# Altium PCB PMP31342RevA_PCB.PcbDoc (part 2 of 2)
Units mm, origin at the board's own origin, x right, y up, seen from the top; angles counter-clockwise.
Board outline 170.18 x 93.98 mm, 4 copper layers (Top Layer, Layer 1, Layer 2, Bottom Layer), stack 1.787 mm thick; 134 components, 50 nets, 251 pads, 234 vias.
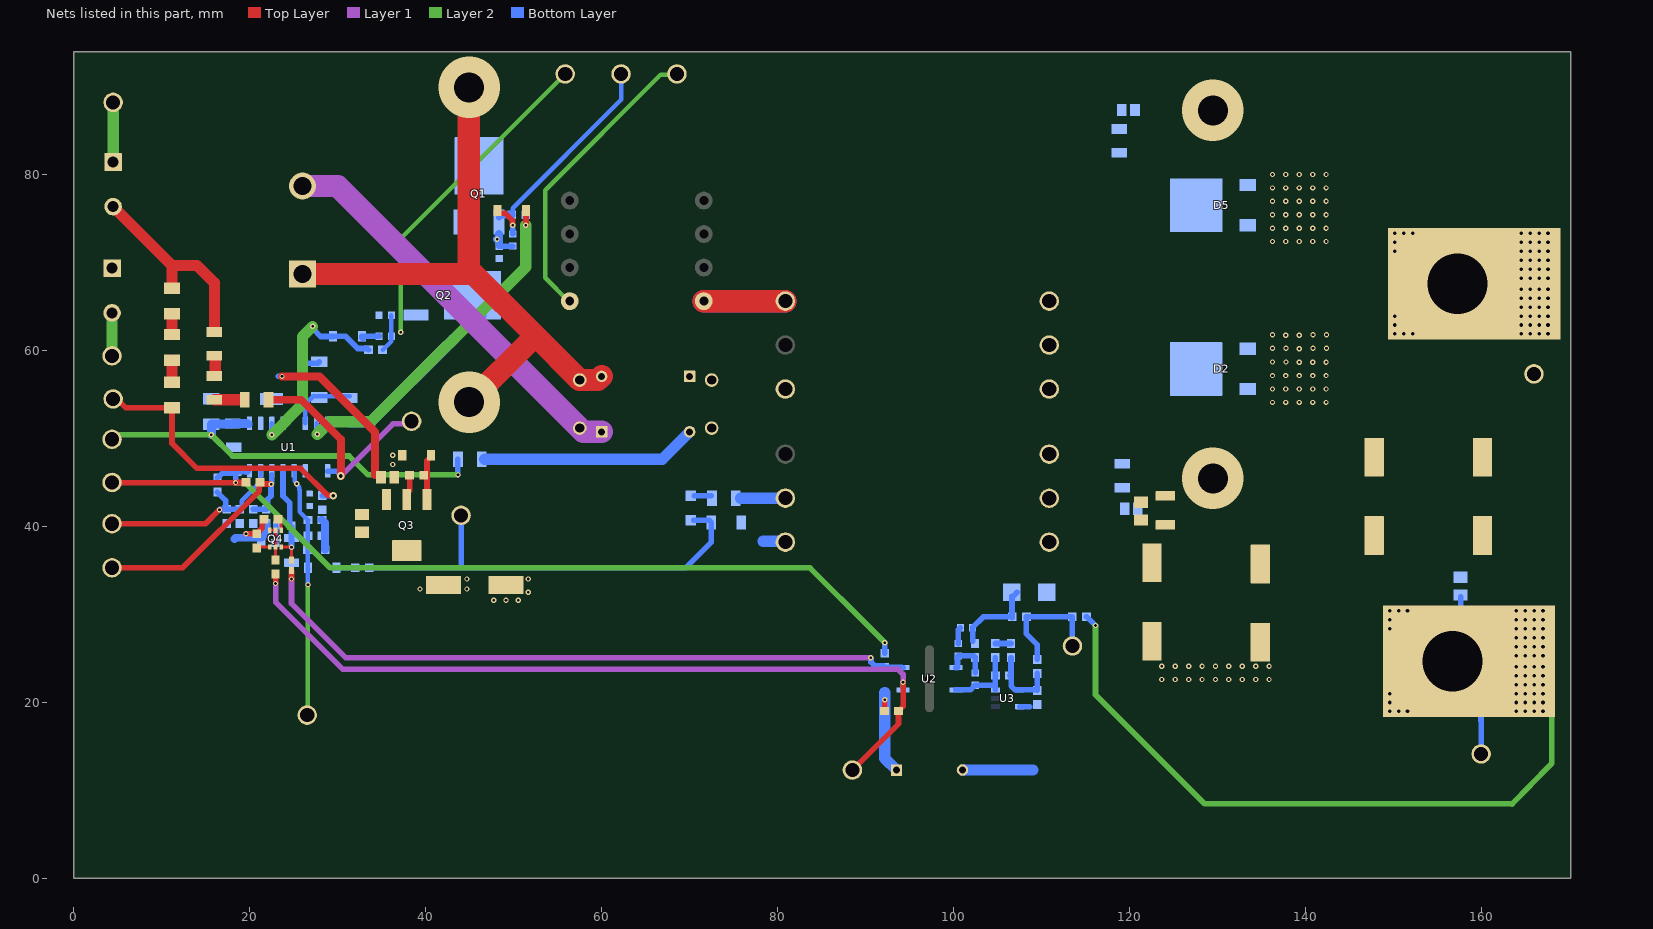
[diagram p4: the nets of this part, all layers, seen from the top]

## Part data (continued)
R31: library part CMP-0022981-5, "RES, 2.05 k, 1%, 0.1 W, 0603", Manufacturer=Yageo, Power_W=100mW, Supplier Part Number 1=311-2.05KHRCT-ND, TempCo="100 ppm/C", Tolerance_%=1%, Value2=0.1W, Value_Code=2k05, ValueDisplayed=2.05k
R32: library part CMP-0022458-4, "RES, 4.99 k, 1%, 0.1 W, AEC-Q200 Grade 0, 0603", Manufacturer=Vishay-Dale, Power_W=100mW, Supplier Part Number 1=541-4.99KHCT-ND, TempCo="100 ppm/C", Tolerance_%=1%, Value2=0.1W, Value_Code=4k99, ValueDisplayed=DNP
R33 R39: library part CMP-0023441-3, "RES, 15.0 k, 0.1%, 0.1 W, 0603", Manufacturer="Susumu Co Ltd", Power_W=100mW, Supplier Part Number 1=RG16P15.0KBCT-ND, TempCo="25 ppm/C", Tolerance_%=0.1%, Value2=0.1W, Value_Code=15k0, ValueDisplayed=15.0k
R34: library part CMP-0022589-4, "RES, 75.0 k, 1%, 0.1 W, AEC-Q200 Grade 0, 0603", Manufacturer=Vishay-Dale, Power_W=100mW, Supplier Part Number 1=541-75.0KHCT-ND, TempCo="100 ppm/C", Tolerance_%=1%, Value2=0.1W, Value_Code=75k0, ValueDisplayed=75.0k
R35: library part CMP-0025697-4, "RES, 0, 5%, 0.1 W, AEC-Q200 Grade 0, 0603", Manufacturer=Vishay-Dale, Power_W=100mW, Supplier Part Number 1=541-0.0GCT-ND, TempCo="200 ppm/C", Tolerance_%=5%, Value2=0.1W, Value_Code=0000, ValueDisplayed=0
R36 R41 R42: library part CMP-0025697-4, "RES, 0, 5%, 0.1 W, AEC-Q200 Grade 0, 0603", Manufacturer=Vishay-Dale, Power_W=100mW, Supplier Part Number 1=541-0.0GCT-ND, TempCo="200 ppm/C", Tolerance_%=5%, Value2=0.1W, Value_Code=0000, ValueDisplayed=DNP
R37: library part CMP-0022634-4, "RES, 8.06 k, 1%, 0.1 W, AEC-Q200 Grade 0, 0603", Manufacturer=Vishay-Dale, Power_W=100mW, Supplier Part Number 1=541-8.06KHCT-ND, TempCo="100 ppm/C", Tolerance_%=1%, Value2=0.1W, Value_Code=8k06, ValueDisplayed=8.06k
R38: library part CMP-0096703-1, "NTC Thermistor 470k 0603 (1608 Metric)", B Tolerance=3%, Digikey Part Number=495-B57371V2474J060CT-ND, Manufacturer=TDK, Mouser Part Number=871-B57371V2474J060, Operating Temperature Range="-55°C to +125°C", Power_W=180mW, Tolerance_%=5%
R40: library part CMP-0022268-4, "RES, 2.00 k, 1%, 0.1 W, AEC-Q200 Grade 0, 0603", Manufacturer=Vishay-Dale, Power_W=100mW, Supplier Part Number 1=541-2.00KHCT-ND, TempCo="100 ppm/C", Tolerance_%=1%, Value2=0.1W, Value_Code=2k00, ValueDisplayed=2.00k
T2 T3: library part CMP-0075010-2, "Terminal 70A Lug", Manufacturer=Panduit, Supplier Part Number 1=CXS70-14-C-ND
TP1 TP2 TP3 TP6 TP7 TP8 TP9 TP10 TP11 TP12 TP13 TP14: library part CMP-0055157-2, "Test Point, Multipurpose, Brown, TH", Color=Brown, Manufacturer="Keystone Electronics", Supplier Part Number 1=36-5125-ND
TP4 TP5 TP15 TP16 TP17 TP18 TP19 TP20: library part CMP-0055140-2, "Test Point, Miniature, Orange, TH", Color=Orange, Manufacturer="Keystone Electronics", Supplier Part Number 1=36-5003-ND
U1: library part CMP-0095298-2, "750kHz Wide VIN/VOUT Range LLC Controller Optimized for Light Load Efficiency", Manufacturer="Texas Instruments", Max Supply Voltage=18.5V, Operating Temperature Range="-40°C to +150°C", PartNumber=UCC256612DDBR, Switching Frequency=30-750kHz
U2: library part CMP-0098363-1, "3.75-kVRMS, Single-Channel Opto-Emulator with Transistor Output", Emiiter Collector Voltage=7V, Forward Current=10mA, Manufacturer="Texas Instruments", Operating Temperature Range="to +150°C", Power_TotalModule=200mW, Voltage_Isolation_Vrms=3750Vrms
U3: library part CMP-0032955-1, "Automotive Catalog Low-Voltage Adjustable Precision Shunt Regulator, 80 mA, -40 to 125 degC, 5-pin SOT-23 (DBV), Green (RoHS & no Sb/Br)", Manufacturer="Texas Instruments", Rating=Automotive, Temp Coeff(Max)(ppm/ degree C)=129

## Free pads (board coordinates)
  oval 1.016x7.62 hole 1.016 slot 7.62 at 90 deg unplated mask+0.127: 3(97.282,22.689)

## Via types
v1: diameter 0.813, hole 0.406, Top Layer to Bottom Layer, 116 vias
v2: diameter 0.6, hole 0.3, Top Layer to Bottom Layer, 112 vias
v3: diameter 7, hole 3.4, Top Layer to Bottom Layer, 4 vias
v4: diameter 0.864, hole 0.406, Top Layer to Bottom Layer, 2 vias

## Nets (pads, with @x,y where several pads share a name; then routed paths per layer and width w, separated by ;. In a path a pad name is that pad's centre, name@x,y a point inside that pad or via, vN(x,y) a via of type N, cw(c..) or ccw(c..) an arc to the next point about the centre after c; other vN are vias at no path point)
5VP: 5V.1 C20.1 R21.2 R22.2 R24.2 U1.8 | length 102.7
  Top Layer w0.635: 5V.1@4.276,44.986 v2(18.41,44.986) 18.421,44.997 19.586,44.997 R22.2@19.596,45.008
  Layer 2 w0.635: v2(18.41,44.986) 19.476,44.986 29.168,35.295 83.704,35.295 90.437,28.562 v2(92.202,26.797)
  Bottom Layer w0.635: R21.2@16.347,45.503 16.347,45.528 16.505,45.685 16.53,45.685 16.91,46.065 18.284,46.065 18.324,46.105 18.42,46.009 18.42,44.996 v2(18.41,44.986) ; R24.2@92.202,25.589 v2(92.202,26.797)
  Bottom Layer w0.889: C20.1@18.324,46.105 C20.1@18.429,46.21 ; C20.1@18.434,46.356 U1.8@19.69,46.316
FB: C27.1 Q4.6 R27.1 R32.2 U1.5 | length 11.7
  Top Layer w0.305: Q4.6@23.601,37.672 23.611,37.662 24.758,37.662 v2(24.768,37.652) R27.1@24.768,36.188
  Bottom Layer w0.635: U1.5@23.798,46.316 23.798,43.466 24.586,42.678 24.586,40.11 24.61,40.11 24.768,39.953 C27.1@24.768,38.688 v2(24.768,37.652)
HO: D1.1 R1.1 U1.15 | length 40.5
  Top Layer w0.635: v2(51.397,74.231) 51.416,74.25 51.416,75.888 D1.1@51.434,75.907
  Layer 2 w1.27: v2(27.691,50.482) 29.117,51.908 33.811,51.908 51.397,69.493 v2(51.397,74.231)
  Bottom Layer w0.508: U1.15@27.608,51.716 27.65,51.675 27.65,50.524 v2(27.691,50.482)
  Bottom Layer w0.635: v2(51.397,74.231) R1.1@51.397,75.432
HS: C21.2 Q1.3 Q2.4 R4.1 SW.1 TP4.1 U1.16 | length 52.3
  Layer 2 w0.508: TP4.1@56.391,65.616 56.25,65.616 53.597,68.269 53.597,78.235 66.713,91.351 68.491,91.351 SW.1@68.58,91.44
  Bottom Layer w0.508: Q2.4@46.698,63.837 Q2.4@46.698,64.066
  Bottom Layer w0.635: 29.178,51.716 C21.2@31.267,51.716
  Bottom Layer w1.27: C21.2@31.369,51.908 33.811,51.908 43.125,61.222 43.157,61.222
ISNS: C7.2 C14.1 ISNS.1 R10.2 U1.9 | length 48.7
  Layer 2 w0.635: ISNS.1@4.334,49.855 4.739,49.855 5.306,50.422 v2(15.646,50.422) 18.063,48.006 31.32,48.006 33.467,45.859 v2(43.684,45.859)
  Bottom Layer w0.635: U1.9@19.972,51.533 19.99,51.55 U1.9@19.99,51.716 ; v2(43.684,45.859) C7.2@43.684,47.648
  Bottom Layer w1.016: v2(15.646,50.422) R10.2@15.646,51.533 ; R10.2@15.646,51.595 15.713,51.662 18.052,51.662 C14.1@18.085,51.695 U1.9@19.69,51.716
LO: D4.1 R6.1 U1.11 | length 23.1
  Layer 2 w1.27: v2(22.53,50.422) 26.016,53.908 26.016,61.594 v2(27.166,62.744)
  Bottom Layer w0.508: v2(22.53,50.422) v2(22.53,50.422) 22.529,51.715 U1.11@22.53,51.716
  Bottom Layer w0.635: v2(27.166,62.744) 27.19,62.72 27.19,62.484 28.08,61.594 D4.1@29.458,61.594 ; D4.1@29.49,61.626 30.9,61.626 32.301,60.226 33.363,60.226 R6.1@33.521,60.068
NetBLK_1: BLK.1 C23.2 R20.1 R28.2 U1.3 | length 33.2
  Top Layer w0.635: BLK.1@4.496,54.499 4.922,54.499 5.913,53.508 R20.1@11.176,53.508 11.176,49.457 14.03,46.603 25.796,46.603 28.853,43.546 29.448,43.546 v4(29.491,43.502)
  Layer 2 w0.635: v4(29.491,43.502) v4@29.534,43.459
  Bottom Layer w0.635: R28.2@28.245,43.508 28.248,43.505 29.489,43.505 v4(29.491,43.502)
NetC1_2: C1.2 C7.1 C12.1 TP3.1 | length 24.6
  Bottom Layer w1.27: C7.1@46.734,47.648 66.912,47.648 C1.2@70.024,50.76
NetC2_1: C2.1 R2.1
NetC16_1: C16.1 R7.1
NetC21_1: C21.1 D7.1 U1.14 | length 7.6
  Bottom Layer w0.508: U1.14@26.34,51.716 26.34,53.918 27.229,54.808 C21.1@31.369,54.808
NetC22_1: C22.1 D8.1 R25.2 R26.1 | length 9.8
  Bottom Layer w0.635: R25.2@102.192,26.965 C22.1@102.192,28.501 102.192,28.526 103.406,29.74 R26.1@106.667,29.74 ; R26.1@106.667,29.611 R26.1@106.667,29.74 ; D8.1@106.667,32.068 D8.1@106.667,31.941 ; R26.1@106.7,29.74 R26.1@106.667,29.74 ; D8.1@107.232,32.506 D8.1@106.667,31.941 ; R26.1@106.667,29.74 D8.1@106.667,31.941
NetC22_2: C22.2 R19.2 | length 1.9
  Bottom Layer w0.635: R19.2@100.572,26.691 100.572,28.256 100.792,28.476 C22.2@100.792,28.501
NetC24_1: C24.1 LL.1 R22.1 R30.2 U1.6 | length 29.5
  Top Layer w0.635: LL.1@4.369,35.306 12.387,35.306 21.116,44.035 21.116,44.744 21.166,44.794 v2(22.457,44.794) 22.423,44.794 22.366,44.85 21.354,44.85 R22.1@21.196,45.008
  Bottom Layer w0.635: R30.2@20.396,41.953 21.92,41.953 22.033,42.066 22.033,43.066 22.433,43.465 22.433,44.769 v2(22.457,44.794) 22.457,44.828 22.53,44.901 U1.6@22.53,45.859
NetC25_1: C25.1 R21.1 R29.2 TSET.1 U1.7 | length 22.5
  Top Layer w0.635: TSET.1@4.369,40.311 14.999,40.311 v2@16.597,41.908
  Bottom Layer w0.508: C25.1@18.877,41.953 19.098,42.174 19.098,42.924 21.258,45.084 U1.7@21.258,46.316
  Bottom Layer w0.635: R21.1@16.347,43.903 16.347,43.878 17.271,42.954 R29.2@17.271,42.346 ; v2(16.579,41.908) 16.614,41.908 16.676,41.97 C25.1@18.877,41.97
NetC26_1: C26.1 D9.2 OVP_OTP.1 R38.2 R39.2 U1.4 | length 28.2
  Top Layer w0.508: OVP_OTP.1@26.551,18.553 OVP_OTP.1@26.598,18.6 ; v2@26.598,33.312 v2(26.645,33.359)
  Layer 2 w0.508: OVP_OTP.1@26.598,18.6 v2@26.598,33.312
  Bottom Layer w0.508: U1.4@25.07,46.316 25.116,46.27 25.116,45.156 25.355,44.917 v2(25.355,44.848) 25.355,44.78 25.665,44.47 25.665,44.167 ; 25.685,41.671 25.685,44.147 ; 25.882,41.473 26.62,40.735 C26.1@26.645,40.735 26.618,40.708 26.618,38.962 26.618,37.389 26.608,37.38 26.608,35.208 26.645,35.171 26.635,35.161 26.635,33.369 v2(26.645,33.359)
NetC28_1: C28.1 R34.1 R37.2 R40.2 U3.4 | length 8.2
  Bottom Layer w0.635: C28.1@106.388,23.057 106.413,23.057 106.57,22.9 106.57,21.874 107.026,21.419 U3.4@107.526,21.419 109.48,21.419 R40.2@109.529,21.371 R34.1@109.529,23.285 ; C28.1@106.55,23.215 R37.2@106.55,25.093
NetC28_2: C28.2 C30.2 R31.1 U2.2 U3.3 | length 9.5
  Bottom Layer w0.635: U2.2@100.282,21.419 101.932,21.419 102.356,21.843 102.356,21.868 102.439,21.951 R31.1@102.464,21.951 104.776,21.951 C30.2@104.776,25.093 ; U3.3@104.776,21.419 104.782,21.425 104.782,23.051 C28.2@104.788,23.057
NetC29_1: C29.1 R32.1 | length 2
  Bottom Layer w0.635: C29.1@22.916,38.127 22.951,38.162 22.951,40.076 R32.1@22.986,40.11
NetC30_1: C30.1 R37.1 | length 1.8
  Bottom Layer w0.635: C30.1@104.776,26.693 R37.1@106.55,26.693
NetD1_2: D1.2 R3.1 | length 3.8
  Top Layer w0.635: D1.2@48.159,75.907 48.159,75.755 48.299,75.615 49.047,75.615 49.887,74.775 49.887,74.256 v2(49.911,74.231)
  Bottom Layer w0.635: v2(49.911,74.231) 49.914,74.229 49.914,73.262 R3.1@49.917,73.259 R3.1@49.942,73.259
NetD3_2: D3.2 R5.1 | length 1.9
  Bottom Layer w0.635: D3.2@70.561,43.507 R5.1@72.464,43.507
NetD4_2: D4.2 R8.1 | length 2.3
  Bottom Layer w0.635: D4.2@32.905,61.334 32.765,61.474 D4.2@32.765,61.626 32.775,61.636 34.71,61.636 R8.1@34.721,61.647
NetD6_1: D6.1 Q3.1 R12.1 | length 5.2
  Top Layer w0.635: Q3.1@40.166,43.054 40.166,47.47 40.626,47.931 D6.1@40.626,48.084
NetD7_2: D7.2 R13.2 | length 2.2
  Bottom Layer w0.635: R13.2@25.886,58.452 25.969,58.535 27.748,58.535 D7.2@27.94,58.727
NetD9_1: D9.1 R33.1 | length 2.1
  Bottom Layer w0.635: D9.1@29.901,35.295 R33.1@32.011,35.295 R33.1@31.999,35.307
NetHG_1: HG.1 Q1.1 R1.2 R3.2 R4.2 | length 25.3
  Bottom Layer w0.305: R1.2@49.797,75.432 R1.2@49.897,75.532
  Bottom Layer w0.508: R1.2@49.897,75.532 49.897,76.186 62.23,88.519 HG.1@62.23,91.44
  Bottom Layer w0.635: R4.2@48.356,71.848 48.361,71.854 49.911,71.854 R3.2@49.917,71.859 ; Q1.1@48.356,75.125 Q1.1@48.663,75.432
  Bottom Layer w0.889: v2(48.133,72.644) v2@48.14,72.644 ; R4.2@48.356,72.229 Q1.1@48.356,73.24 ; Q1.1@48.663,75.432 R1.2@49.797,75.432
NetHV_1: HV.1 R17.2 U1.1 | length 26.9
  Top Layer w0.889: R17.2@22.155,54.408 25.882,54.408 30.378,49.911 v4(30.378,45.733)
  Layer 1 w0.635: v4(30.378,45.733) 36.3,51.655 38.118,51.655 HV.1@38.419,51.956
  Layer 2 w0.508: v4(30.378,45.733) v4@30.475,45.733
  Bottom Layer w0.635: U1.1@28.895,46.288 29.932,46.288 30.13,46.09 30.13,46.043 30.378,45.795 v4(30.378,45.733) ; HV.1@38.419,51.85 HV.1@38.546,51.723
NetI_opt_1: I_opt.1 R35.2 R36.2 U2.3 | length 91.7
  Top Layer w0.635: v2(22.951,33.522) R36.2@22.951,34.588 ; I_opt.1@88.519,12.313 93.764,17.558 R35.2@93.764,19.028 93.789,19.028 93.946,19.185 93.946,19.21 94.282,19.546 v2(94.282,22.277)
  Layer 1 w0.635: v2(22.951,33.522) 22.951,31.405 30.607,23.749 93.717,23.749 94.282,23.184 v2(94.282,22.277)
  Bottom Layer w0.635: 94.282,21.719 v2(94.282,22.277)
NetINJ_1: Inj.1 R23.1 R26.2 R34.2 | length 13.9
  Bottom Layer w0.635: R26.2@108.3,29.74 108.3,27.791 109.529,26.562 R34.2@109.529,24.885 ; R26.2@108.3,29.749 R23.1@113.519,29.749 113.529,29.74 113.529,26.42 Inj.1@113.538,26.41
NetLG_1: LG.1 Q2.1 R6.2 R8.2 R9.2 | length 41.5
  Layer 2 w0.508: v2(37.181,62.077) 37.181,72.741 LG.1@55.88,91.44
  Bottom Layer w0.508: R6.2@35.121,60.068 35.146,60.068 36.121,61.043 R8.2@36.121,61.647 R9.2@36.121,64.009
NetQ4_1: Q4.1 R41.2 | length 1.4
  Top Layer w0.305: R41.2@23.223,40.801 23.248,40.801 23.57,40.479 23.57,39.603 Q4.1@23.601,39.572
NetQ4_2: Q4.2 Q4.3 Q4.5 R36.1 | length 3.9
  Top Layer w0.305: Q4.3@22.301,39.572 22.797,39.572 22.951,39.418 Q4.5@22.951,37.672 R36.1@22.951,36.188
NetQ4_4: Q4.4 R42.2 | length 1.5
  Top Layer w0.305: R42.2@20.816,37.566 20.922,37.672 Q4.4@22.301,37.672
NetR5_2: R5.2 TP12.1 | length 5.1
  Bottom Layer w1.27: R5.2@75.812,43.216 TP12.1@80.899,43.216
NetR14_1: R14.1 R18.2 | length 2.4
  Top Layer w1.27: R18.2@11.176,61.818 R14.1@11.176,64.178
NetR15_2: R15.2 R16.1 | length 1.7
  Top Layer w1.27: R16.1@16.098,57.32 R15.2@16.098,58.978
NetR16_2: R16.2 R17.1 | length 3.4
  Top Layer w1.27: R16.2@16.002,54.408 19.239,54.408 R17.1@19.33,54.499
NetR18_1: R18.1 R20.2 | length 2.5
  Top Layer w1.27: R20.2@11.176,56.408 R18.1@11.176,58.918
NetR19_1: R19.1 R25.1 R31.2 U2.1 | length 5.3
  Bottom Layer w0.635: U2.1@100.282,23.959 100.447,23.959 100.465,23.977 100.465,25.209 100.547,25.291 R19.1@100.572,25.291 102.29,25.291 102.464,25.118 R25.1@102.464,25.093 R31.2@102.464,23.351
NetR24_1: R24.1 R27.2 U2.4 | length 76.6
  Top Layer w0.635: v2(24.768,34.03) R27.2@24.768,34.988
  Layer 1 w0.635: v2(24.768,34.03) 24.768,31.239 30.944,25.063 v2(90.614,25.063)
  Bottom Layer w0.635: v2(90.614,25.063) 90.639,25.038 90.639,24.583 91.05,24.172 92.044,24.172 92.217,23.999 92.217,23.974 U2.4@94.157,23.974 ; U2.4@94.154,23.977 U2.4@94.157,23.974 ; U2.4@94.282,23.959 94.172,23.959 U2.4@94.157,23.974
NetT1_2: TP5.1 TP6.1 | length 18.5
  Top Layer w2.54: TP5.1@71.631,65.616 TP6.1@80.899,65.616
  Layer 1 w2.54: TP5.1@71.631,65.616 TP6.1@80.899,65.616
PGND: C3.1 C12.2 C13.2 C14.2 C15.2 C17.1 C18.1 C19.2 C20.2 C23.1 C24.2 C25.2 C26.2 C27.2 C29.2 D6.2 J2.1 J2.2 PGND.1 Q2.3 R9.1 R10.1 R28.1 R29.1 R30.1 R35.1 R38.1 R39.1 R41.1 R42.1 TP9.1 U1.10 | length 100.9
  Top Layer w0.635: v2(19.596,39.166) R42.1@20.816,39.166 20.816,39.191 21.44,39.815 21.44,40.644 21.598,40.801 R41.1@21.623,40.801 ; R35.1@92.164,19.028 92.183,19.047 92.183,20.299 v2(92.202,20.318)
  Top Layer w2.54: C3.1@26.016,68.698 45.468,68.698 ; v3(44.958,54.13) 52.356,61.528 52.356,61.81 ; v3(44.958,89.916) 44.908,89.866 44.908,69.258 45.468,68.698 ; C12.2@60.024,57.063 59.603,56.642 C12.2@57.524,56.642 52.356,61.81 ; 45.468,68.698 52.356,61.81
  Layer 2 w1.27: PGND.1@4.369,59.401 J2.2@4.369,64.282
  Bottom Layer w0.889: 18.279,38.58 18.41,38.711 21.355,38.711 21.876,39.231 C24.2@21.876,40.353 ; C26.2@28.19,40.766 28.22,40.735 C26.2@28.245,40.735 ; R38.1@28.59,37.362 C26.2@28.59,40.415
  Bottom Layer w1.27: C12.2@57.524,56.642 C12.2@57.578,56.696 ; C12.2@60.016,57.063 C12.2@60.024,57.063 ; 78.362,38.319 80.566,38.319 TP9.1@80.792,38.093 ; 92.202,21.134 v2(92.202,20.318) 92.202,13.643 C17.1@93.532,12.313
  other v2: 47.752,31.617 49.143,31.617 50.546,31.617 51.689,32.516 51.689,34.03 36.264,47.04 36.264,48.084
SGND: C2.2 C4.1 C5.1 C6.1 C8.1 C9.1 C10.2 C11.2 C16.2 C17.2 D2.1 D2.2 D5.1 D5.2 D8.2 R40.1 SGND.1 T3.1 U3.5 | length 9.2
  Bottom Layer w0.635: U3.5@107.526,19.519 108.696,19.519
  Bottom Layer w1.27: C17.2@101.032,12.313 109.054,12.313
  other v1: 150.162,61.884 151.178,61.884 152.194,61.884 164.545,61.884 165.561,61.884 166.577,61.884 167.593,61.884 150.162,62.9 164.545,62.9 165.561,62.9 166.577,62.9 167.593,62.9 150.162,63.916 164.545,63.916 165.561,63.916 166.577,63.916 167.593,63.916 164.545,64.932 165.561,64.932 166.577,64.932 167.593,64.932 164.545,65.948 165.561,65.948 166.577,65.948 167.593,65.948 164.545,66.964 165.561,66.964 166.577,66.964 167.593,66.964 164.545,68.234 165.561,68.234 166.577,68.234 167.593,68.234 164.545,69.25 165.561,69.25 166.577,69.25 167.593,69.25 164.545,70.266 165.561,70.266 166.577,70.266 167.593,70.266 150.162,71.282 164.545,71.282 165.561,71.282 166.577,71.282 167.593,71.282 150.162,72.298 164.545,72.298 165.561,72.298 166.577,72.298 167.593,72.298 150.162,73.314 151.178,73.314 152.194,73.314 164.545,73.314 165.561,73.314 166.577,73.314 167.593,73.314
  other v2: 123.698,22.6 125.222,22.6 126.746,22.6 128.27,22.6 129.794,22.6 131.318,22.6 132.842,22.6 134.366,22.6 135.89,22.6 123.698,24.124 125.222,24.124 126.746,24.124 128.27,24.124 129.794,24.124 131.318,24.124 132.842,24.124 134.366,24.124 135.89,24.124 136.271,54.102 137.795,54.102 139.319,54.102 140.843,54.102 142.367,54.102 136.271,55.626 137.795,55.626 139.319,55.626 140.843,55.626 142.367,55.626 136.271,57.15 137.795,57.15 139.319,57.15 140.843,57.15 142.367,57.15 139.319,58.674 140.843,58.674 142.367,58.674 136.271,58.699 137.812,58.699 139.319,60.198 136.271,60.26 137.812,60.26 140.884,60.26 142.408,60.26 137.795,61.722 139.319,61.722 136.271,61.784 140.884,61.784 142.408,61.784 136.271,72.39 137.795,72.39 139.319,72.39 140.843,72.39 142.367,72.39 136.271,73.914 137.795,73.914 139.319,73.914 140.843,73.914 142.367,73.914 136.271,75.438 137.795,75.438 139.319,75.438 140.843,75.438 142.367,75.438 136.271,76.962 137.795,76.962 139.319,76.962 140.843,76.962 142.367,76.962 136.271,78.486 137.795,78.486 139.319,78.486 140.843,78.486 142.367,78.486 136.271,80.01 137.795,80.01 139.319,80.01 140.843,80.01 142.367,80.01
  other v3: 129.507,45.462 129.507,87.294
VAUX: C13.1 C15.1 D3.1 Q3.2 Q3.4 R11.2 R12.2 R33.2 VAUX.1 | length 53.3
  Top Layer w0.635: Q3.2@37.866,43.054 37.866,43.754 38.189,44.078 R12.2@38.189,45.818
  Bottom Layer w0.635: R33.2@33.611,35.295 41.486,35.295 44.069,35.295 ; VAUX.1@44.043,41.266 44.043,35.321 44.069,35.295 ; D3.1@70.5,40.711 72.228,40.711 C15.1@72.484,40.454 72.484,38.215 69.564,35.295 44.069,35.295
  other v2: 39.37,32.887 44.704,32.887 44.704,34.03
VCC: C18.2 C19.1 Q3.3 R11.1 R13.1 U1.12 | length 21.1
  Top Layer w0.635: C18.2@34.583,45.825 C18.2@34.816,45.592
  Top Layer w0.889: v2(23.684,57.056) 27.945,57.056 34.266,50.735 34.266,45.859
  Layer 1 w0.635: v2(23.684,57.056) v2@23.708,57.031
  Bottom Layer w0.635: 23.277,57.056 v2(23.684,57.056) 23.827,57.056 23.83,57.052 R13.1@25.886,57.052
VD1: D5.3 R7.2 TP10.1 TP11.1
VD2: D2.3 R2.2 TP1.1 TP2.1
VIN: C1.1 C3.2 J1.1 J1.2 Q1.4 R14.2 R15.1 Vin.1 | length 75.2
  Top Layer w1.27: J1.2@4.496,76.347 11.176,69.666 ; R14.2@11.176,67.078 11.176,69.666 ; 16.002,62.651 16.002,67.695 14.03,69.666 11.176,69.666
  Layer 1 w2.54: C3.2@26.016,78.698 30.007,78.698 C1.1@57.524,51.181 57.945,50.76 C1.1@60.024,50.76
  Layer 2 w1.27: J1.1@4.496,81.427 Vin.1@4.496,88.208
  Bottom Layer w1.27: C1.1@57.524,51.181 C1.1@57.578,51.127
Vout: C4.2 C5.2 C6.2 C8.2 C9.2 C10.1 C11.1 R23.2 T2.1 TP7.1 TP8.1 Vout.1 | length 86.4
  Layer 2 w0.635: v2(116.158,28.736) 116.158,20.875 128.573,8.46 163.467,8.46 163.5,8.427 167.842,12.898 168.021,13.082 T2.1@168.021,19.267
  Bottom Layer w0.635: R23.2@115.119,29.749 115.144,29.749 v2(116.158,28.736) ; T2.1@157.658,28.772 157.658,31.693 C11.1@157.658,31.997 ; T2.1@158.684,19.18 T2.1@158.684,20.627 ; T2.1@159.979,21.351 Vout.1@159.994,14.139
  other v1: 149.592,18.976 150.608,18.976 151.624,18.976 163.976,18.976 164.992,18.976 166.008,18.976 167.024,18.976 149.592,19.992 163.976,19.992 164.992,19.992 166.008,19.992 167.024,19.992 149.592,21.008 163.976,21.008 164.992,21.008 166.008,21.008 167.024,21.008 163.976,22.024 164.992,22.024 166.008,22.024 167.024,22.024 163.976,23.04 164.992,23.04 166.008,23.04 167.024,23.04 163.976,24.056 164.992,24.056 166.008,24.056 167.024,24.056 163.976,25.326 164.992,25.326 166.008,25.326 167.024,25.326 163.976,26.342 164.992,26.342 166.008,26.342 167.024,26.342 163.976,27.358 164.992,27.358 166.008,27.358 167.024,27.358 149.592,28.374 163.976,28.374 164.992,28.374 166.008,28.374 167.024,28.374 149.592,29.39 163.976,29.39 164.992,29.39 166.008,29.39 167.024,29.39 149.592,30.406 150.608,30.406 151.624,30.406 163.976,30.406 164.992,30.406 166.008,30.406 167.024,30.406
pads on no net: TP13.1 TP14.1 TP15.1 TP16.1 TP17.1 TP18.1 TP19.1 TP20.1 U3.1 U3.2
copper on no net: | length 0
  Top Layer w0.152: 175.59,58.567 175.59,58.575

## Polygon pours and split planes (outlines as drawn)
PGND on Top Layer "TOP_LAYER_PGND_P116" (solid, pour order 116): 35.766,45.859 35.566,46.059 35.566,48.699 36.03,49.163 37.794,49.163 38.316,48.641 38.316,47.332 37.056,46.073 36.866,46.073 36.866,46.013 36.712,45.859
PGND on Top Layer "TOP_LAYER_PGND_P112" (solid, pour order 112): 47.143,34.538 47.143,31.343 47.498,30.988 51.435,30.988 52.324,31.877 52.324,34.092 51.878,34.538
VCC on Top Layer "TOP_LAYER_VCC_P109" (solid, pour order 109): 31.75,43.97 34.072,46.292 35.366,46.292 35.366,45.28 36.316,44.33 36.316,41.581 35.473,40.738 31.915,40.738 31.75,40.903
VAUX on Top Layer "Top Layer-VAUX" (solid, pour order 108): 38.735,32.506 39.352,31.889 44.73,31.889 45.339,32.498 45.339,34.538 43.823,36.054 38.366,41.512 38.366,43.637 37.394,43.637 37.366,43.665 37.366,41.911 35.766,40.311 32.084,40.311 31.75,39.976 31.75,38.622 35.456,34.917 37.849,34.917 38.735,34.03
Vout on Top Layer "TOP_LAYER_VOUT_P010" (solid, remove dead copper, pour order 10): 168.421,38.837 165.895,41.362 120.255,41.362 116.674,44.943 108.232,44.943 108.232,34.307 112.666,30.226 137.706,30.226 137.706,26.219 145.871,18.054 168.421,18.054
SGND on Top Layer "TOP_LAYER_SGND_P092" (solid, pour order 92): 120.218,29.792 120.218,20.879 123.044,18.053 145.871,18.053 145.871,29.792
SGND on Top Layer "TOP_LAYER_SGND_P078" (solid, remove dead copper, pour order 78): 137.548,75.432 137.516,75.4 137.516,71.444 142.822,71.444 143.281,71.904 143.281,75.534
SGND on Top Layer "TOP_LAYER_SGND_P076" (solid, remove dead copper, pour order 76): 165.788,41.455 169.088,44.755 169.088,92.98 121.375,92.98 116.796,88.345 116.796,41.455
SGND on Top Layer "TOP_LAYER_SGND_P080" (solid, remove dead copper, pour order 80): 136.652,62.123 136.677,62.097 143.18,62.097 143.18,56.738 137.795,56.738 137.795,57.254 136.641,58.409
PGND on Bottom Layer "BOTTOM_LAYER_PGND_P118" (solid, pour order 118): 40.63,93.472 40.63,87.63 40.64,87.63 41.91,86.36 47.781,86.36 47.781,86.389 49.022,87.63 49.022,93.472
PGND on Bottom Layer "BOTTOM_LAYER_PGND_P117" (solid, pour order 117): 40.767,55.867 43.627,58.727 46.632,58.727 49.492,55.867 49.492,52.475 47.032,50.015 42.976,50.015 40.767,52.224
PGND on Bottom Layer "BOTTOM_LAYER_PGND_P111" (solid, pour order 111): 30.162,42.832 31.259,42.832 35.366,46.939 35.366,48.513 35.621,48.768 36.712,48.768 37.02,48.46 37.02,45.852 31.428,40.26 30.071,40.26
PGND on Bottom Layer "Bottom Layer-PGND" (solid, remove dead copper, pour order 106): 7.62,61.334 7.62,28.021 9.689,25.953 22.942,25.953 30.342,18.553 91.313,18.553 92.684,18.553 93.264,19.132 93.218,19.178 93.218,22.698 92.632,23.285 91.313,23.285 91.313,29.337 80.772,39.878 78.719,39.878 77.343,41.254 75.934,41.254 75.934,39.878 75.438,39.878 70.022,34.462 31.414,34.462 31.414,42.852 26.495,42.852 26.495,41.81 27.445,41.81 27.445,34.24 25.99,34.24 25.99,40.627 26.026,40.663 26.026,41.353 23.89,41.353 23.881,41.361 23.786,41.266 23.786,40.903 21.973,40.903 19.547,40.903 19.547,42.732 22.228,45.412 22.228,58.971 26.22,62.962 22.109,62.962 33.87,62.962 35.121,62.962 35.213,63.054 35.213,64.984 37.185,66.956 39.498,66.956 40.472,67.929 40.472,70.557 2.54,70.557 2.54,62.962 5.982,62.962 7.611,61.334
HS on Bottom Layer "Bottom Layer-HS" (solid, pour order 97): 42.106,61.609 43.172,60.543 53.942,60.543 56.475,63.076 58.293,64.894 58.293,66.251 57.631,66.913 55.334,66.913 49.833,70.936 47.479,70.936 45.974,72.441 45.974,76.021 43.236,76.021 43.078,75.864 43.078,71.533 42.106,70.561
VIN on Bottom Layer "BOTTOM_LAYER_VIN_P054" (solid, remove dead copper, pour order 54): 2.492,84.348 27.838,84.348 28.454,84.963 52.807,84.963 52.807,81.045 49.457,77.695 36.045,77.695 32.121,73.772 2.492,73.772
NetC16_1 on Bottom Layer "BOTTOM_LAYER_NETC16_1_P008" (solid, pour order 8): 117.083,84.309 117.083,88.045 117.591,88.553 119.109,88.553 119.876,87.786 119.876,84.35 119.366,83.84 117.552,83.84
VAUX on Bottom Layer "BOTTOM_LAYER_VAUX_P012" (solid, pour order 12): 38.735,34.538 38.735,35.295 44.582,35.295 45.339,34.538 45.339,32.498 44.73,31.889 39.352,31.889 38.735,32.506
NetC2_1 on Bottom Layer "BOTTOM_LAYER_NETC2_1_P028" (solid, pour order 28): 117.55,41.664 118.154,41.06 120.046,41.06 120.046,45.107 119.818,45.335 118.135,45.335 117.55,44.75
NetC1_2 on Bottom Layer "BOTTOM_LAYER_NETC1_2_P094" (solid, pour order 94): 69.129,57.738 69.843,58.452 80.782,58.452 82.296,56.938 82.296,53.791 78.198,49.693 70.171,49.693 69.129,50.736
NetLG_1 on Bottom Layer "BOTTOM_LAYER_NETLG_1_P089" (solid, pour order 89): 35.621,61.222 38.419,61.222 40.361,63.164 40.361,64.664 40.041,64.984 36.07,64.984 35.621,64.534
VCC on Bottom Layer "BOTTOM_LAYER_VCC_P087" (solid, remove dead copper, pour order 87): 22.843,58.205 23.49,58.852 24.525,58.852 24.525,56.021 24.553,55.993 24.553,53.537 24.313,53.537 24.275,53.5 24.275,50.947 23.5,50.947 23.5,53.388 22.843,53.388 22.843,57.558
VD2 on Bottom Layer "BOTTOM_LAYER_VD2_P042" (solid, remove dead copper, pour order 42): 124.206,46.502 131.827,54.102 131.827,69.342 108.232,69.342 108.232,46.502
VD1 on Bottom Layer "BOTTOM_LAYER_VD1_P040" (solid, remove dead copper, pour order 40): 113.98,58.42 124.902,69.342 131.819,69.342 131.801,80.258 128.676,83.382 112.395,83.382 108.232,79.22 108.232,58.42
NetBLK_1 on Bottom Layer "BOTTOM_LAYER_NETBLK_1_P088" (solid, remove dead copper, pour order 88): 26.04,47.04 26.04,45.592 26.353,45.279 26.353,43.552 26.495,43.41 28.495,43.41 28.495,44.031 26.97,45.556 26.97,47.076 26.055,47.076
SGND on Bottom Layer "BOTTOM_LAYER_SGND_P044" (solid, remove dead copper, pour order 44): 108.232,93.002 108.232,7.665 169.037,7.665 169.037,92.953
no net on Bottom Layer "BOTTOM_LAYER_NONET_P082" (solid, remove dead copper, pour order 82): 17.628,50.845 20.396,50.845 20.396,54.782 17.628,54.782
Vout on Layer 1 "LAYER_1_VOUT_P115" (solid, remove dead copper, pour order 115): 168.421,38.837 165.895,41.362 120.255,41.362 116.678,44.939 108.232,44.939 108.232,34.307 112.666,30.226 137.706,30.226 137.706,26.219 145.871,18.054 168.421,18.054

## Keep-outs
Keep-Out Layer:
  text ".Layer_Name" at 14.656,-42.132 h1.02

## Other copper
Top Layer:
  text ".Layer_Name" at 14.656,-42.132 h1.02
Bottom Layer:
  region net Vout: 147.14,20.987 148.022,20.105 148.022,19.16 148.841,18.341 168.925,18.341 168.925,31.109 147.14,31.109
  text ".Layer_Name" at 14.656,-42.132 h1.02

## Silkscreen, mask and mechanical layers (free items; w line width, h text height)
Top Overlay:
  text "Vin: 225Vdc to 450Vdc" at 1.524,91.567 h1.02
  text "L1" at 62.484,79.624 h1.02
  text "T1" at 89.789,69.68 h1.02
  text "'.PRJ_Number'Rev.SCH_Rev" at 15.621,2.737 h1.02
  text "48Vdc 7A max" at 155.651,2.407 h1.02
  text ".Layer_Name" at 14.656,-42.132 h1.02
Bottom Overlay:
  text ".Layer_Name" at 14.656,-42.132 h1.02
Top Paste:
  text ".Layer_Name" at 14.656,-42.132 h1.02
Bottom Paste:
  text ".Layer_Name" at 14.656,-42.132 h1.02
Top Solder:
  text ".Layer_Name" at 14.656,-42.132 h1.02
  text ".Layer_Name" at 14.656,-42.132 h1.02
Bottom Solder:
  text ".Layer_Name" at 14.656,-42.132 h1.02
Drill Guide:
  text ".Layer_Name" at 14.656,-42.132 h1.02
M1 Board Outline:
  the board outline again, w1
  text ".Layer_Name" at 14.656,-42.132 h1.02
M2 Board Dimensions:
  rectangle: 3.175,-30.486 12.7,-27.311
  rectangle: 0,-27.311 3.175,-24.136
  lines w0.178: 0,-27.311 25.4,-27.311 ; 3.175,-30.486 3.175,-24.136 ; 6.35,-30.486 6.35,-24.136 ; 12.7,-30.486 12.7,-24.136 ; 19.05,-30.486 19.05,-24.136 ; 0,-30.486 0,-24.136 25.4,-24.136 25.4,-30.486 0,-30.486
  text ".Layer_Name" at 14.656,-42.132 h1.02
M3 3D STEP Top:
  text ".Layer_Name" at 14.656,-42.132 h1.02
M4 3D STEP Bottom:
  text ".Layer_Name" at 14.656,-42.132 h1.02
M5 Assembly Top:
  lines w0.254: -7.417,-43.952 160.223,-43.952 ; -7.417,-38.787 160.274,-38.787 ; -7.417,-33.623 -7.417,-49.117 94.31,-49.117 160.274,-49.117 160.274,-33.623 -7.404,-33.623 -7.404,-49.117 32.614,-49.117 ; 55.194,-49.117 55.194,-33.623 ; 87.376,-38.787 87.376,-33.623 ; 108.712,-38.787 108.712,-33.623 ; 124.511,-49.282 124.511,-44.13
  text "COMPONENTS MARKED 'DNP' SHOULD NOT BE POPULATED." at 29.299,-28.416 h1.02
  text "ASSEMBLY VARIANT:" at 29.286,-31.349 h1.02
  text ".VariantName" at 55.601,-31.349 h1.02
  text "PCB VIEWED FROM TOP SIDE" at -5.804,-36.98 h1.02
  text "BOARD #:" at 57.099,-36.98 h1.02
  text ".PRJ_Number" at 70.955,-36.98 h1.02
  text "REV:" at 92.405,-36.98 h1.02
  text ".PCB_Rev" at 99.809,-36.98 h1.02
  text "SVN REV:" at 113.69,-36.98 h1.02
  text ".VersionControl_RevNumber" at 126.543,-36.98 h1.02
  text "TID #:" at 57.099,-42.144 h1.02
  text ".TID" at 70.955,-42.144 h1.02
  text "PLOT NAME =" at -5.804,-47.36 h1.02
  text ".plot_File_Name" at 14.656,-47.36 h1.02
  text "GENERATED    :" at 57.15,-47.36 h1.02
  text ".Print_Date" at 79.235,-47.36 h1.02
  text ".Print_Time" at 97.752,-47.36 h1.02
  text "TEXAS INSTRUMENTS" at 129.87,-47.36 h1.02
M6 Assembly Bottom:
  lines w0.254: -7.429,-38.8 160.261,-38.8 ; -7.379,-43.965 160.261,-43.965 ; 28.334,-49.295 28.334,-44.143 ; 44.133,-38.8 44.133,-33.635 ; 65.468,-38.8 65.468,-33.635 ; 97.65,-49.129 97.65,-33.635 ; 120.231,-49.129 160.249,-49.129 160.249,-33.635 -7.429,-33.635 -7.429,-49.129 58.534,-49.129 160.261,-49.129 160.261,-33.635
  text "COMPONENTS MARKED 'DNP' SHOULD NOT BE POPULATED." at 154.991,-28.403 h1.02
  text ".VariantName" at 128.473,-31.349 h1.02
  text "ASSEMBLY VARIANT:" at 154.864,-31.349 h1.02
  text ".VersionControl_RevNumber" at 26.302,-36.992 h1.02
  text "SVN REV:" at 39.154,-36.992 h1.02
  text ".PCB_Rev" at 53.035,-36.992 h1.02
  text "REV:" at 60.439,-36.992 h1.02
  text ".PRJ_Number" at 81.89,-36.992 h1.02
  text "BOARD #:" at 95.745,-36.992 h1.02
  text "PCB VIEWED FROM BOTTOM SIDE" at 158.648,-36.992 h1.02
  text ".TID" at 81.89,-42.157 h1.02
  text "TID #:" at 95.745,-42.157 h1.02
  text "TEXAS INSTRUMENTS" at 22.974,-47.373 h1.02
  text ".Print_Time" at 55.093,-47.373 h1.02
  text ".Print_Date" at 73.609,-47.373 h1.02
  text "GENERATED    :" at 95.694,-47.373 h1.02
  text ".plot_File_Name" at 138.189,-47.373 h1.02
  text "PLOT NAME =" at 158.648,-47.373 h1.02
M9 Title Sheet:
  drawing of 57 lines, arcs and shapes, not listed
  text "1" at 18.792,183.801 h1.02
  text "2" at 82.182,183.801 h1.02
  text "3" at 145.411,183.801 h1.02
  text "4" at 209.08,183.801 h1.02
  text "5" at 272.555,183.801 h1.02
  text "6" at 336.182,183.801 h1.02
  text "A" at -10.579,154.769 h1.02
  text "A" at 365.341,154.769 h1.02
  text "B" at -10.579,94.317 h1.02
  text "B" at 365.341,94.317 h1.02
  text "C" at -10.579,33.992 h1.02
  text "C" at 365.341,33.992 h1.02
  text "PROJECT TITLE:" at 288.125,-13.277 h1.14
  text ".PRJ_Title" at 289.395,-16.664 h1.02
  text "DESIGNED FOR:" at 288.125,-20.923 h1.14
  text ".PRJ_Customer" at 289.395,-24.479 h1.02
  text "D" at -10.579,-26.206 h1.02
  text "D" at 365.341,-26.206 h1.02
  text "FILE NAME:" at 288.125,-28.543 h1.14
  text ".PCB_File_Name_No_Path" at 289.395,-31.591 h1.02
  text "Texas Instruments (TI) and/or its licensors do not warrant the accuracy or completeness of this specification" at 161.9,-35.701 h1.02
  text "ENGINEER:" at 288.125,-35.909 h1.14
  text "LAYOUT BY:" at 326.352,-35.909 h1.14
  text "or any information contained therein. TI and/or its licensors do not warrant that this design will meet" at 160.757,-38.563 h1.02
  text ".PRJ_Engineer" at 289.395,-39.846 h1.02
  text ".PCB_Layout" at 327.635,-39.846 h1.02
  text "the specifications, will be suitable for your application or fit for any particular purpose, or will operate in" at 160.757,-41.425 h1.02
  text ".Layer_Name" at 14.656,-42.132 h1.02
  text "ALTIUM DESIGNER VERSION:" at 326.352,-43.783 h1.14
  text "an implementation. TI and/or its licensors do not warrant that the design is production worthy. You should" at 160.757,-44.287 h1.02
  text "completely validate and test your design implementation to confirm the system functionality for your application." at 161.9,-47.148 h1.02
  text ".print_Scale" at 289.395,-47.169 h1.02
  text ".Application_BuildNumber" at 327.635,-47.169 h1.02
  text "1" at 18.792,-52.419 h1.02
  text "2" at 82.182,-52.419 h1.02
  text "3" at 145.411,-52.419 h1.02
  text "4" at 209.08,-52.419 h1.02
  text "5" at 272.555,-52.419 h1.02
  text "6" at 336.182,-52.419 h1.02
M10 Fab Notes:
  drawing of 189 lines, arcs and shapes, not listed
  text "DESIGN INFORMATION" at 314.503,141.121 h1.02
  text "MIN. TRACK WIDTH:" at 298.131,137.765 h1.02
  text "8" at 325.976,137.765 h1.02
  text "MIL" at 329.907,137.765 h1.02
  text "MIN. CLEARANCE:" at 298.131,134.612 h1.02
  text "0.2" at 324.452,134.612 h1.02
  text "mm" at 329.907,134.612 h1.02
  text "MIN. VIA PAD SIZE:" at 298.131,131.459 h1.02
  text "24" at 325.214,131.459 h1.02
  text "MIL" at 329.907,131.459 h1.02
  text "0.05mm (2MIL)" at 315.784,128.16 h1.02
  text "MINIMUM ANNULAR RING" at 289.769,127.951 h1.02
  text "EXTERNAL" at 333.768,127.951 h1.02
  text "PER" at 294.849,125.154 h1.02
  text "IPC-D-275 CLASS 2 LEVEL C" at 300.437,125.154 h1.02
  text "MIL, HOLES" at 338.238,122.602 h1.02
  text "+/-" at 328.27,122.384 h1.02
  text "+/-" at 349.961,122.384 h1.02
  text "REGISTRATION TOLERANCES:" at 289.769,122.357 h1.02
  text "METAL" at 320.243,122.357 h1.02
  text "5" at 334.879,122.357 h1.02
  text "3" at 356.037,122.357 h1.02
  text "MIL" at 358.99,122.357 h1.02
  text "HOLE SIZE TOLERANCE (UNLESS OTHERWISE SPECIFIED):" at 289.769,119.859 h1.02
  text "+/-" at 349.961,119.786 h1.02
  text "3" at 356.037,119.759 h1.02
  text "MIL" at 358.99,119.759 h1.02
  text "MATERIAL:" at 287.87,116.263 h1.02
  text "FR-4 High Tg" at 312.926,112.999 h1.02
  text "X" at 309.257,112.796 h1.02
  text "FR-408" at 298.563,112.681 h1.02
  text "OTHER" at 336.358,112.681 h1.02
  text "62 MIL (1.6mm) +/-10%" at 306.694,109.048 h1.02
  text "X" at 303.643,108.986 h1.02
  text "THICKNESS:" at 289.769,108.839 h1.02
  text "OTHER" at 339.33,108.839 h1.02
  text "TOLERANCE:" at 289.769,105.326 h1.02
  text "X" at 311.314,105.326 h1.02
  text "ANSI IPC-6012 TYPE 3 CLASS 2" at 315.836,105.326 h1.02
  text "OTHER +/-" at 315.835,101.664 h1.02
  text "BOW & TWIST:" at 289.769,97.976 h1.02
  text "X" at 311.314,97.976 h1.02
  text "ANSI IPC-6012 TYPE 3 CLASS 2" at 315.836,97.976 h1.02
  text "OTHER +/-" at 315.835,94.25 h1.02
  text "DRILLING:" at 287.87,90.932 h1.02
  text "NC_DRILL FILES" at 332.599,88.26 h1.02
  text "REFERENCE:" at 289.769,88.16 h1.02
  text "X" at 306.463,88.158 h1.02
  text "AS SHOWN" at 310.984,88.16 h1.02
  text "X" at 329.348,88.16 h1.02
  text "OTHER" at 340.168,84.547 h1.02
  text "PTH COPPER THICKNESS:" at 289.761,84.457 h1.02
  text "X" at 318.697,84.457 h1.02
  text "20-30 um" at 321.948,84.457 h1.02
  text "BOARD FINISH:" at 287.87,80.708 h1.02
  text "SILKSCREEN:" at 291.812,77.911 h1.02
  text "X" at 316.14,77.911 h1.02
  text "TOP" at 319.112,77.911 h1.02
  text "X" at 329.094,77.911 h1.02
  text "BOTTOM" at 332.091,77.911 h1.02
  text "SILKSCREEN COLOR:" at 291.812,73.969 h1.02
  text "X" at 316.115,73.969 h1.02
  text "WHITE" at 319.112,73.969 h1.02
  text "OTHER" at 332.091,73.969 h1.02
  text "X" at 319.442,70.326 h1.02
  text "GREEN" at 322.439,70.326 h1.02
  text "OTHER" at 338.136,70.326 h1.02
  text "SOLDER RESIST COLOR:" at 291.812,70.151 h1.02
  text "X" at 319.442,66.408 h1.02
  text "MATTE" at 322.439,66.408 h1.02
  text "SEMI-GLOSS" at 338.125,66.392 h1.02
  text "IMMERSION GOLD (ENIG)" at 314.819,62.019 h1.02
  text "ENEPIG" at 348.793,61.836 h1.02
  text "SURFACE FINISH:" at 287.87,61.811 h1.02
  text "X" at 310.298,61.811 h1.02
  text "IMM. TIN/SILVER OR EQUIV" at 296.24,58.323 h1.02
  text "OTHER" at 332.599,58.223 h1.02
  text "ARRAY/PANEL:" at 287.87,54.276 h1.02
  text "CUT AND TRIM PER M1 BOARD OUTLINE" at 314.819,54.067 h1.02
  text "N.C. ROUTE" at 314.819,50.614 h1.02
  text "X" at 332.295,50.614 h1.02
  text "V. SCORE" at 336.816,50.614 h1.02
  text "CERTIFICATION:" at 287.87,47.334 h1.02
  text "MATERIALS AND WORKMANSHIP FOR ALL PCBS" at 306.285,47.334 h1.02
  text "TO MEET OR EXCEED THE REQUIREMENTS OF:" at 306.285,44.945 h1.02
  text "X" at 297.078,41.678 h1.02
  text "ANSI IPC-A-600F CLASS ->" at 300.329,41.678 h1.02
  text "X" at 342.188,41.678 h1.02
  text "2" at 344.982,41.678 h1.02
  text "1" at 336.981,41.64 h1.02
  text "3" at 353.973,41.64 h1.02
  text "X" at 317.702,37.926 h1.02
  text "RoHS" at 320.953,37.926 h1.02
  text "OTHER" at 337.321,37.926 h1.02
  text "PER ORDER" at 347.407,37.926 h1.02
  text "ALL BOARDS MUST MEET OR EXCEED UL94-V0 REQUIREMENTS." at 288.569,34.019 h1.02
  text "PCB MUST BEAR THE UL94V-0 UL REGISTERED MATERIAL ID NUMBER" at 288.569,31.071 h1.02
  text "ADDITIONAL REQUIREMENTS:" at 287.87,26.768 h1.02
  text "MICROSECTION:" at 289.769,24.047 h1.02
  text "YES" at 312.775,24.047 h1.02
  text "REQUIRED" at 334.657,20.381 h1.02
  text "BARE BOARD ELEC. TEST:" at 289.769,20.308 h1.02
  text "NONE" at 322.935,20.308 h1.02
  text "X" at 331.66,20.308 h1.02
  text "PER ORDER" at 349.693,20.308 h1.02
  text "XX MIL VIAS REQUIRE NON-CONDUCTIVE FILL AND PLANARIZE" at 294.04,15.103 h1.5
  text "XX MIL VIAS REQUIRE CONDUCTIVE FILL AND PLANARIZE" at 294.243,12.462 h1.02
  text "OUTER XX MIL TRACES REQUIRE 50 OHM SINGLE-ENDED IMPEDANCE" at 294.218,8.312 h1.47
  text "LAYER 2 & 3 (INNER LAYERS) XX MIL WIDE, XX MIL SPACE / TRACES REQUIRE 100 OHM DIFFERENTIAL IMPEDANCE" at 294.015,2.324 h1.02
  text ".Layer_Name" at 14.656,-42.132 h1.02
M11 Gerber Information:
  lines w0.254: -7.417,-43.952 160.223,-43.952 ; -7.417,-38.787 160.274,-38.787 ; -7.417,-33.623 -7.417,-49.117 94.31,-49.117 160.274,-49.117 160.274,-33.623 -7.404,-33.623 -7.404,-49.117 32.614,-49.117 ; 55.194,-49.117 55.194,-33.623 ; 87.376,-38.787 87.376,-33.623 ; 108.712,-38.787 108.712,-33.623 ; 124.511,-49.282 124.511,-44.13
  text "ALL ARTWORK VIEWED FROM TOP SIDE" at -5.804,-36.98 h1.02
  text "BOARD #:" at 57.099,-36.98 h1.02
  text ".PRJ_Number" at 70.955,-36.98 h1.02
  text "REV:" at 92.405,-36.98 h1.02
  text ".PCB_Rev" at 99.809,-36.98 h1.02
  text "SVN REV:" at 113.69,-36.98 h1.02
  text ".VersionControl_RevNumber" at 126.543,-36.98 h1.02
  text "LAYER NAME =" at -5.804,-42.132 h1.02
  text "TID #:" at 57.099,-42.144 h1.02
  text ".TID" at 70.955,-42.144 h1.02
  text "PLOT NAME =" at -5.804,-47.36 h1.02
  text ".plot_File_Name" at 14.656,-47.36 h1.02
  text "GENERATED    :" at 57.15,-47.36 h1.02
  text ".Print_Date" at 79.235,-47.36 h1.02
  text ".Print_Time" at 97.752,-47.36 h1.02
  text "TEXAS INSTRUMENTS" at 129.87,-47.36 h1.02
M12 Stackup:
  drawing of 295 lines, arcs and shapes, not listed
  text "Layer" at 113.119,142.958 h1.02
  text "Name" at 120.229,142.958 h1.02
  text "Material" at 136.142,142.958 h1.02
  text "Thickness" at 150.871,142.958 h1.02
  text "Constant" at 162.044,142.958 h1.02
  text "Board Layer Stack" at 171.863,142.958 h1.02
  text "Top Overlay" at 120.229,140.926 h1.02
  text "Top Solder" at 120.229,138.894 h1.02
  text "Solder Resist" at 136.142,138.894 h1.02
  text "0.40mil" at 150.871,138.894 h1.02
  text "3.5" at 162.044,138.894 h1.02
  text "1" at 113.119,136.862 h1.02
  text "Top Layer" at 120.229,136.862 h1.02
  text "2.80mil" at 150.871,136.862 h1.02
  text "Dielectric 1" at 120.229,134.83 h1.02
  text "PP-006" at 136.142,134.83 h1.02
  text "2.80mil" at 150.871,134.83 h1.02
  text "4.1" at 162.044,134.83 h1.02
  text "2" at 113.119,132.798 h1.02
  text "Layer 1" at 120.229,132.798 h1.02
  text "CF-004" at 136.142,132.798 h1.02
  text "1.38mil" at 150.871,132.798 h1.02
  text "Dielectric1" at 120.229,130.766 h1.02
  text "FR-4 High Tg" at 136.142,130.766 h1.02
  text "56.40mil" at 150.871,130.766 h1.02
  text "4.8" at 162.044,130.766 h1.02
  text "3" at 113.119,128.734 h1.02
  text "Layer 2" at 120.229,128.734 h1.02
  text "CF-004" at 136.142,128.734 h1.02
  text "1.38mil" at 150.871,128.734 h1.02
  text "Dielectric 2" at 120.229,126.702 h1.02
  text "PP-006" at 136.142,126.702 h1.02
  text "2.80mil" at 150.871,126.702 h1.02
  text "4.1" at 162.044,126.702 h1.02
  text "4" at 113.119,124.67 h1.02
  text "Bottom Layer" at 120.229,124.67 h1.02
  text "2.80mil" at 150.871,124.67 h1.02
  text "Bottom Solder" at 120.229,122.638 h1.02
  text "Solder Resist" at 136.142,122.638 h1.02
  text "0.40mil" at 150.871,122.638 h1.02
  text "3.5" at 162.044,122.638 h1.02
  text "Bottom Overlay" at 120.229,120.606 h1.02
  text ".Layer_Name" at 14.656,-42.132 h1.02
M13 Component Bodies Top:
  text ".Layer_Name" at 14.656,-42.132 h1.02
M14 Component Bodies Bottom:
  text ".Layer_Name" at 14.656,-42.132 h1.02
M15 Courtyards Top:
  text ".Layer_Name" at 14.656,-42.132 h1.02
M16 Courtyards Bottom:
  text ".Layer_Name" at 14.656,-42.132 h1.02
Drill Drawing:
  circle w0.254: c185.601,14.013 r0.468
  lines w0.254: 185.133,-3.296 185.601,-3.062 186.069,-3.296 185.835,-2.829 186.069,-2.361 185.601,-2.595 185.133,-2.361 185.367,-2.829 185.133,-3.296 ; 185.133,-0.256 186.069,-0.256 185.601,-1.191 185.133,-0.256 ; 185.133,1.148 185.367,1.148 185.601,0.914 185.835,1.148 186.069,1.148 185.835,1.382 186.069,1.616 185.835,1.616 185.601,1.85 185.367,1.616 185.133,1.616 185.367,1.382 185.133,1.148 ; 185.133,3.019 186.069,3.019 186.069,3.955 185.133,3.955 185.133,3.019 ; 185.133,7.463 185.367,7.463 185.367,7.229 185.835,7.229 185.835,7.463 186.069,7.463 186.069,7.931 185.835,7.931 185.835,8.165 185.367,8.165 185.367,7.931 185.133,7.931 185.133,7.463 ; 185.133,9.568 185.367,9.568 185.367,9.335 185.835,9.335 185.835,9.568 186.069,9.568 186.069,10.036 185.835,10.036 185.835,10.27 185.367,10.27 185.367,10.036 185.133,10.036 185.133,9.568 ; 185.133,15.65 185.133,15.884 185.367,16.118 185.133,16.352 185.133,16.586 185.367,16.586 185.601,16.352 185.835,16.586 186.069,16.586 186.069,16.352 185.835,16.118 186.069,15.884 186.069,15.65 185.835,15.65 185.601,15.884 185.367,15.65 185.133,15.65 ; 185.32,7.557 185.46,7.557 185.46,7.417 185.741,7.417 185.741,7.557 185.881,7.557 185.881,7.838 185.741,7.838 185.741,7.978 185.46,7.978 185.46,7.838 185.32,7.838 185.32,7.557
  lines w0.305: 184.258,-6.033 237.732,-6.033 ; 184.258,17.124 237.732,17.124 ; 189.979,-8.138 189.979,19.229 ; 195.098,-8.138 195.098,19.229 ; 205.136,-8.138 205.136,19.229 ; 209.524,-8.138 209.524,19.229 ; 215.876,-8.138 215.876,19.229 ; 228.141,-8.138 228.141,19.229 ; 184.258,-8.138 237.732,-8.138 237.732,19.229 184.258,19.229 184.258,-8.138
  text "Symbol" at 185.521,17.755 h1.22
  text "Count" at 190.611,17.755 h1.22
  text "Hole Size" at 195.73,17.755 h1.22
  text "Plated" at 205.768,17.755 h1.22
  text "Hole Type" at 210.155,17.755 h1.22
  text "Drill Layer Pair" at 216.507,17.755 h1.22
  text "Hole Tolerance" at 228.773,17.755 h1.22
  text "112" at 190.611,15.65 h1.02
  text "11.81mil (0.300mm)" at 195.73,15.65 h1.02
  text "PTH" at 205.768,15.65 h1.02
  text "Round" at 210.155,15.65 h1.02
  text "Top Layer - Bottom Layer" at 216.507,15.65 h1.02
  text "118" at 190.611,13.545 h1.02
  text "16.00mil (0.406mm)" at 195.73,13.545 h1.02
  text "PTH" at 205.768,13.545 h1.02
  text "Round" at 210.155,13.545 h1.02
  text "Top Layer - Bottom Layer" at 216.507,13.545 h1.02
  text "6" at 190.611,11.44 h1.02
  text "31.50mil (0.800mm)" at 195.73,11.44 h1.02
  text "PTH" at 205.768,11.44 h1.02
  text "Round" at 210.155,11.44 h1.02
  text "Top Layer - Bottom Layer" at 216.507,11.44 h1.02
  text "F" at 185.035,11.186 h0.94
  text "8" at 190.611,9.335 h1.02
  text "40.00mil (1.016mm)" at 195.73,9.335 h1.02
  text "PTH" at 205.768,9.335 h1.02
  text "Round" at 210.155,9.335 h1.02
  text "Top Layer - Bottom Layer" at 216.507,9.335 h1.02
  text "1" at 190.611,7.229 h1.02
  text "40.00mil (1.016mm)" at 195.73,7.229 h1.02
  text "NPTH" at 205.768,7.229 h1.02
  text "Slot" at 210.155,7.229 h1.02
  text "Top Layer - Bottom Layer" at 216.507,7.229 h1.02
  text "4" at 190.611,5.124 h1.02
  text "41.34mil (1.050mm)" at 195.73,5.124 h1.02
  text "PTH" at 205.768,5.124 h1.02
  text "Round" at 210.155,5.124 h1.02
  text "Top Layer - Bottom Layer" at 216.507,5.124 h1.02
  text "C" at 185.035,4.87 h0.94
  text "4" at 190.611,3.019 h1.02
  text "49.21mil (1.250mm)" at 195.73,3.019 h1.02
  text "PTH" at 205.768,3.019 h1.02
  text "Round" at 210.155,3.019 h1.02
  text "Top Layer - Bottom Layer" at 216.507,3.019 h1.02
  text "29" at 190.611,0.914 h1.02
  text "63.00mil (1.600mm)" at 195.73,0.914 h1.02
  text "PTH" at 205.768,0.914 h1.02
  text "Round" at 210.155,0.914 h1.02
  text "Top Layer - Bottom Layer" at 216.507,0.914 h1.02
  text "2" at 190.611,-1.191 h1.02
  text "78.74mil (2.000mm)" at 195.73,-1.191 h1.02
  text "PTH" at 205.768,-1.191 h1.02
  text "Round" at 210.155,-1.191 h1.02
  text "Top Layer - Bottom Layer" at 216.507,-1.191 h1.02
  text "4" at 190.611,-3.296 h1.02
  text "133.86mil (3.400mm)" at 195.73,-3.296 h1.02
  text "PTH" at 205.768,-3.296 h1.02
  text "Round" at 210.155,-3.296 h1.02
  text "Top Layer - Bottom Layer" at 216.507,-3.296 h1.02
  text "2" at 190.611,-5.402 h1.02
  text "270.00mil (6.858mm)" at 195.73,-5.402 h1.02
  text "PTH" at 205.768,-5.402 h1.02
  text "Round" at 210.155,-5.402 h1.02
  text "Top Layer - Bottom Layer" at 216.507,-5.402 h1.02
  text "D" at 185.035,-5.655 h0.94
  text "290 Total" at 190.611,-7.507 h1.02
  text "Slot definitions :" at 185.521,-8.98 h1.02
  text "Routed Path Length" at 193.154,-8.98 h1.02
  text "= Calculated from tool start centre position to tool end centre position." at 202.293,-8.98 h1.02
  text "Hole Length" at 193.154,-9.822 h1.02
  text "= Routed Path Length + Tool Size = Slot length as defined in the PCB layout" at 198.91,-9.822 h1.02
  text ".Layer_Name" at 14.656,-42.132 h1.02
M17 Embedded Cavity:
  text ".Layer_Name" at 14.656,-42.132 h1.02
M18 Embedded Assembly:
  text ".Layer_Name" at 14.656,-42.132 h1.02
M19 Embedded Keepout:
  text ".Layer_Name" at 14.656,-42.132 h1.02

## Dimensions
0,-0.006 to 170.18,-0.006 on M2 Board Dimensions
0,-0.006 to 0,93.974 on M2 Board Dimensions
0,-30.486 to 25.4,-30.486 on M2 Board Dimensions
